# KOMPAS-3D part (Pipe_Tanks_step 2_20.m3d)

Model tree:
1. X Axis
2. Y Axis
3. Z Axis  (labels: Valve Dy 50; Pipe Dn 50)
     Òîëùèíà ñòåíêè 1 = 1

Referenced files in C:\Documents and Settings\kashirsky\Мои документы\Camtasia Studio\Pipelines3D\Tanks\: Tanks_step 2.a3d
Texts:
  Pipe Dn 50
  Steel ASTM A295
  Three Point Plane
  Plane at Angle
  Line and Point Plane
  Axis through Two Vertices
  Axis of Feature
  Axis of Conical Surface
  Axis through Edge
  Trim by Surface
  Trim by Sketch
  Feature with No History
  Intersection Axis of Two Planes
  Two Line Plane
  Line and Face Plane
  Bend by line
  Hole in sheet body
  Cut in sheet body
  Point in CM
  Linear Dimension from Line to Point
  Surface Finish Symbol
  Geometric Tolerance Symbol
  Leader #1
  Leader #2
  Leader #3
  Shape Deviations and Datum
  Node point number
  Mark of coordination axis
  Node point designation
  Mark/Reference designation with leader
  Mark/reference designation on line
  Mark/Reference designation without leader
  Valve Dy 50
  Plane of section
